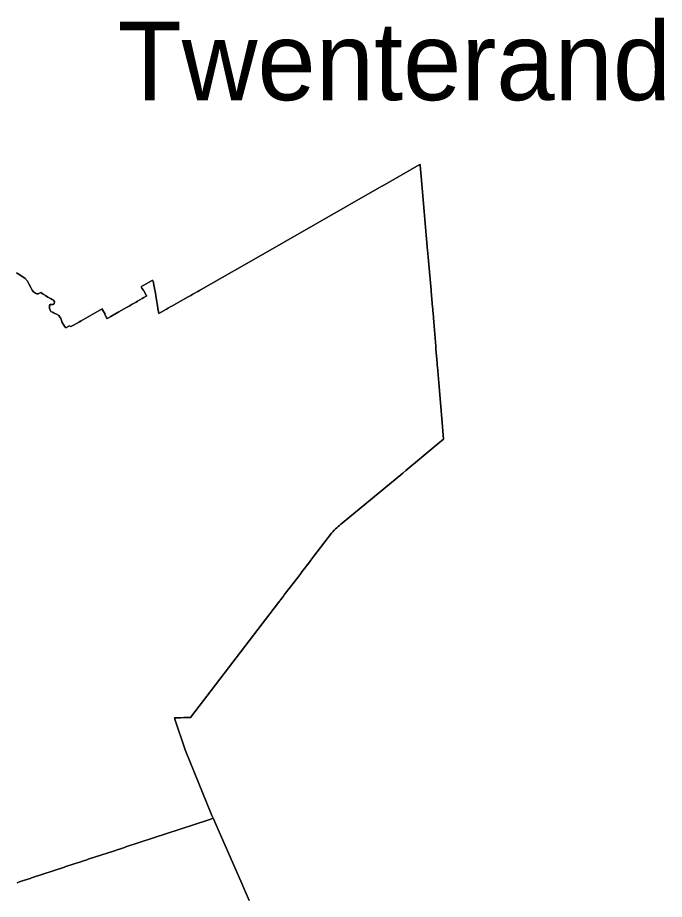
# Model space of a CAD drawing. Extents: x 113371 to 291721, y 393993 to 520143.
# Drawn here: x 234596 to 238723, y 492353 to 497979 of the extents above; entities that cross this region are included whole.
import ezdxf

# ---------------------------------------------------------------- set-up
doc = ezdxf.new("R2010")
doc.units = 0
doc.layers.add('Default', color=7, linetype='Continuous')
doc.layers.add('plaatsnamen', color=7, linetype='Continuous')

msp = doc.modelspace()

# ---------------------------------------------------------------- linework, layer by layer
at = {"layer": 'Default'}
for points in [[(237244.255625, 496130.8725), (237235.055625, 496230.9125), (237234.175625, 496241.0325), (237224.205625, 496356.3625), (237216.105625, 496449.9825), (237213.815625, 496476.4325), (237212.355625, 496493.2425), (237171.465625, 496966.0125), (237165.395625, 497036.2125), (237165.175625, 497038.7025), (237164.825625, 497042.7225), (237164.815625, 497042.7125), (237157.815625, 497038.7225), (236922.145625, 496904.2925), (236921.915625, 496904.1625), (236921.185625, 496903.7425), (236088.645625, 496428.1525), (235856.755625, 496295.9625), (235756.915625, 496238.7625), (235745.675625, 496232.3325), (235745.545625, 496232.2625), (235713.965625, 496214.2225), (235713.875625, 496214.1725), (235700.665625, 496206.6325), (235689.175625, 496200.0425), (235681.025625, 496195.3925), (235580.535625, 496138.0025), (235575.095625, 496135.0625), (235560.105625, 496126.9425), (235557.805625, 496125.6925), (235556.855625, 496125.1825), (235546.935625, 496119.4925), (235497.485625, 496091.0225), (235491.985625, 496124.0025), (235488.835625, 496142.9125), (235487.045625, 496153.7925), (235483.075625, 496177.6425), (235473.675625, 496233.7825)], [(235689.175625, 496200.0425), (235700.665625, 496206.6325), (235713.875625, 496214.1725), (235713.965625, 496214.2225), (235745.545625, 496232.2625), (235745.675625, 496232.3325), (235756.915625, 496238.7625), (235856.755625, 496295.9625), (236088.645625, 496428.1525), (236921.185625, 496903.7425), (236921.915625, 496904.1625), (236922.145625, 496904.2925), (237157.815625, 497038.7225), (237164.815625, 497042.7125), (237164.825625, 497042.7225), (237165.175625, 497038.7025), (237165.395625, 497036.2125), (237171.465625, 496966.0125), (237212.355625, 496493.2425), (237213.815625, 496476.4325), (237216.105625, 496449.9825), (237224.205625, 496356.3625), (237234.175625, 496241.0325), (237235.055625, 496230.9125), (237244.255625, 496130.8725), (237245.225625, 496121.8025), (237246.575625, 496107.4925), (237247.805625, 496093.1525), (237252.315625, 496035.0125), (237264.125625, 495883.0325), (237265.545625, 495864.7025), (237273.005625, 495777.2025), (237274.305625, 495761.9525), (237275.155625, 495751.9325), (237283.985625, 495648.3625), (237303.565625, 495421.8025), (237313.875625, 495289.2825), (237278.365625, 495258.6725)], [(234760.145625, 496215.5825), (234743.595625, 496224.3225), (234727.305625, 496216.8825), (234718.665625, 496216.0025), (234710.255625, 496220.9725), (234697.965625, 496229.0925), (234690.125625, 496240.1525), (234680.615625, 496256.3625), (234668.055625, 496280.8825), (234662.595625, 496293.1425), (234660.665625, 496295.4525), (234644.625625, 496314.5025), (234611.485625, 496338.9725), (234589.775625, 496351.2025)], [(234589.775625, 496351.2025), (234611.485625, 496338.9725), (234644.625625, 496314.5025), (234660.665625, 496295.4525), (234662.595625, 496293.1425), (234668.055625, 496280.8825), (234680.615625, 496256.3625), (234690.125625, 496240.1525), (234697.965625, 496229.0925), (234710.255625, 496220.9725), (234718.665625, 496216.0025), (234727.305625, 496216.8825), (234743.595625, 496224.3225), (234760.145625, 496215.5825), (234774.145625, 496205.4025), (234788.735625, 496194.5425), (234805.665625, 496185.8925), (234816.465625, 496180.4825), (234824.865625, 496175.5425), (234830.675625, 496165.2225), (234830.505625, 496153.2325), (234828.505625, 496150.4825), (234820.925625, 496149.4725), (234815.825625, 496148.4325), (234803.835625, 496148.6125), (234800.555625, 496142.6825), (234799.965625, 496124.0025)], [(235473.675625, 496233.7825), (235472.625625, 496240.0925), (235462.325625, 496297.5025), (235459.205625, 496300.3425), (235458.565625, 496300.9725), (235455.365625, 496301.1925), (235450.325625, 496299.8625), (235430.985625, 496288.6725), (235386.885625, 496263.5925), (235387.845625, 496259.8325), (235390.035625, 496251.2625), (235390.725625, 496251.5825), (235390.965625, 496250.9025), (235398.485625, 496239.0325), (235399.415625, 496239.4725), (235401.455625, 496235.8725), (235417.125625, 496208.2725), (235420.135625, 496203.0825), (235420.115625, 496203.0725), (235401.595625, 496192.4525), (235391.185625, 496186.4825), (235376.135625, 496177.8525), (235361.105625, 496169.2325), (235352.645625, 496164.3825), (235344.185625, 496159.5325), (235327.265625, 496149.8325), (235308.185625, 496138.8925), (235286.515625, 496126.4625), (235243.165625, 496101.6025), (235201.785625, 496077.7225), (235191.425625, 496071.7325), (235172.005625, 496060.5325), (235167.755625, 496058.0725), (235152.055625, 496085.2625), (235154.695625, 496086.7525), (235138.945625, 496115.1925), (235137.385625, 496118.0225), (235136.215625, 496120.1325)], [(235344.185625, 496159.5325), (235352.645625, 496164.3825), (235361.105625, 496169.2325), (235376.135625, 496177.8525), (235391.185625, 496186.4825), (235401.595625, 496192.4525), (235420.115625, 496203.0725), (235420.135625, 496203.0825), (235417.125625, 496208.2725), (235401.455625, 496235.8725), (235399.415625, 496239.4725), (235398.485625, 496239.0325), (235390.965625, 496250.9025), (235390.725625, 496251.5825), (235390.035625, 496251.2625), (235387.845625, 496259.8325), (235386.885625, 496263.5925), (235430.985625, 496288.6725), (235450.325625, 496299.8625), (235455.365625, 496301.1925), (235458.565625, 496300.9725), (235459.205625, 496300.3425), (235462.325625, 496297.5025), (235472.625625, 496240.0925), (235473.675625, 496233.7825), (235483.075625, 496177.6425), (235487.045625, 496153.7925), (235488.835625, 496142.9125), (235491.985625, 496124.0025), (235497.485625, 496091.0225), (235546.935625, 496119.4925), (235556.855625, 496125.1825), (235557.805625, 496125.6925), (235560.105625, 496126.9425), (235575.095625, 496135.0625), (235580.535625, 496138.0025), (235681.025625, 496195.3925), (235689.175625, 496200.0425)], [(235136.215625, 496120.1325), (235121.805625, 496111.9425), (235001.585625, 496043.9425), (234995.055625, 496040.2525), (234993.255625, 496039.2225), (234987.955625, 496036.2125), (234985.335625, 496034.7225), (234941.255625, 496009.6425), (234935.965625, 496006.6325), (234929.235625, 496012.5425), (234929.045625, 496012.7325), (234923.675625, 496009.9925), (234904.735625, 495999.0225), (234899.185625, 496004.0425), (234890.335625, 496016.7225), (234881.715625, 496034.3825), (234873.125625, 496059.4525), (234860.085625, 496077.4825), (234844.575625, 496087.0925), (234829.085625, 496094.0425), (234823.715625, 496096.6425), (234823.465625, 496096.7925), (234808.615625, 496104.5025), (234803.615625, 496111.5225), (234799.965625, 496124.0025), (234800.555625, 496142.6825), (234803.835625, 496148.6125), (234815.825625, 496148.4325), (234820.925625, 496149.4725), (234828.505625, 496150.4825), (234830.505625, 496153.2325), (234830.675625, 496165.2225), (234824.865625, 496175.5425), (234816.465625, 496180.4825), (234805.665625, 496185.8925), (234788.735625, 496194.5425), (234774.145625, 496205.4025), (234760.145625, 496215.5825)], [(234799.965625, 496124.0025), (234803.615625, 496111.5225), (234808.615625, 496104.5025), (234823.465625, 496096.7925), (234823.715625, 496096.6425), (234829.085625, 496094.0425), (234844.575625, 496087.0925), (234860.085625, 496077.4825), (234873.125625, 496059.4525), (234881.715625, 496034.3825), (234890.335625, 496016.7225), (234899.185625, 496004.0425), (234904.735625, 495999.0225), (234923.675625, 496009.9925), (234929.045625, 496012.7325), (234929.235625, 496012.5425), (234935.965625, 496006.6325), (234941.255625, 496009.6425), (234985.335625, 496034.7225), (234987.955625, 496036.2125), (234993.255625, 496039.2225), (234995.055625, 496040.2525), (235001.585625, 496043.9425), (235121.805625, 496111.9425), (235136.215625, 496120.1325), (235137.385625, 496118.0225), (235138.945625, 496115.1925), (235154.695625, 496086.7525), (235152.055625, 496085.2625), (235167.755625, 496058.0725), (235172.005625, 496060.5325), (235191.425625, 496071.7325), (235201.785625, 496077.7225), (235243.165625, 496101.6025), (235286.515625, 496126.4625), (235308.185625, 496138.8925), (235327.265625, 496149.8325), (235344.185625, 496159.5325)], [(236403.685625, 494433.4425), (236410.915625, 494442.8825), (236435.505625, 494474.9725), (236442.535625, 494483.8225), (236446.595625, 494488.7725), (236447.385625, 494489.8625), (236468.125625, 494518.1525), (236465.945625, 494513.7925), (236468.155625, 494516.6825), (236487.265625, 494542.3325), (236598.675625, 494689.3125), (236607.025625, 494699.2925), (236615.315625, 494707.9625), (236624.385625, 494716.9425), (236632.595625, 494724.3225), (236641.755625, 494732.1225), (236650.825625, 494739.3525), (236659.775625, 494746.7525), (236667.355625, 494752.9225), (236861.005625, 494913.9225), (237053.415625, 495073.5225), (237072.595625, 495089.7925), (237161.565625, 495162.5325), (237175.705625, 495174.1725), (237278.365625, 495258.6725), (237313.875625, 495289.2825), (237303.565625, 495421.8025), (237283.985625, 495648.3625), (237275.155625, 495751.9325), (237274.305625, 495761.9525), (237273.005625, 495777.2025), (237265.545625, 495864.7025), (237264.125625, 495883.0325), (237252.315625, 496035.0125), (237247.805625, 496093.1525), (237246.575625, 496107.4925), (237245.225625, 496121.8025), (237244.255625, 496130.8725)], [(237278.365625, 495258.6725), (237175.705625, 495174.1725), (237161.565625, 495162.5325), (237072.595625, 495089.7925), (237053.415625, 495073.5225), (236861.005625, 494913.9225), (236667.355625, 494752.9225), (236659.775625, 494746.7525), (236650.825625, 494739.3525), (236641.755625, 494732.1225), (236632.595625, 494724.3225), (236624.385625, 494716.9425), (236615.315625, 494707.9625), (236607.025625, 494699.2925), (236598.675625, 494689.3125), (236487.265625, 494542.3325), (236468.155625, 494516.6825), (236465.945625, 494513.7925), (236468.125625, 494518.1525), (236447.385625, 494489.8625), (236446.595625, 494488.7725), (236442.535625, 494483.8225), (236435.505625, 494474.9725), (236410.915625, 494442.8825), (236403.685625, 494433.4425), (236383.405625, 494406.9225), (236298.085625, 494295.3425), (236291.895625, 494287.2525), (236285.935625, 494279.4925), (236274.085625, 494264.0425), (236271.865625, 494261.1925), (236269.705625, 494258.4125), (236261.685625, 494247.9025), (235698.535625, 493513.9225), (235659.075625, 493513.0325), (235656.135625, 493512.9725), (235634.795625, 493512.6225), (235633.985625, 493512.6125)], [(234917.605625, 492566.4025), (234938.025625, 492573.1025), (234964.185625, 492581.6925), (234993.695625, 492591.3725), (234999.475625, 492593.2725), (235009.705625, 492596.6225), (235037.895625, 492605.8825), (235047.195625, 492608.9325), (235214.085625, 492663.7225), (235238.345625, 492671.6825), (235240.325625, 492672.3325), (235278.395625, 492684.8225), (235287.465625, 492687.8025), (235809.845625, 492859.2725), (235816.175625, 492861.3625), (235833.145625, 492866.9325), (235844.055625, 492870.5025), (235835.805625, 492889.2925), (235666.335625, 493306.3625), (235599.715625, 493502.8925), (235596.585625, 493512.0725), (235600.805625, 493512.0625), (235617.145625, 493512.3325), (235626.085625, 493512.4825), (235633.985625, 493512.6125), (235634.795625, 493512.6225), (235656.135625, 493512.9725), (235659.075625, 493513.0325), (235698.535625, 493513.9225), (236261.685625, 494247.9025), (236269.705625, 494258.4125), (236271.865625, 494261.1925), (236274.085625, 494264.0425), (236285.935625, 494279.4925), (236291.895625, 494287.2525), (236298.085625, 494295.3425), (236383.405625, 494406.9225), (236403.685625, 494433.4425)], [(235633.985625, 493512.6125), (235626.085625, 493512.4825), (235617.145625, 493512.3325), (235600.805625, 493512.0625), (235596.585625, 493512.0725), (235599.715625, 493502.8925), (235666.335625, 493306.3625), (235835.805625, 492889.2925), (235844.055625, 492870.5025), (236020.275625, 492468.7525), (236074.375625, 492345.4125)], [(236074.375625, 492345.4125), (236020.275625, 492468.7525), (235844.055625, 492870.5025), (235833.145625, 492866.9325), (235816.175625, 492861.3625), (235809.845625, 492859.2725), (235287.465625, 492687.8025), (235278.395625, 492684.8225), (235240.325625, 492672.3325), (235238.345625, 492671.6825), (235214.085625, 492663.7225), (235047.195625, 492608.9325), (235037.895625, 492605.8825), (235009.705625, 492596.6225), (234999.475625, 492593.2725), (234993.695625, 492591.3725), (234964.185625, 492581.6925), (234938.025625, 492573.1025), (234917.605625, 492566.4025), (234898.315625, 492560.0725), (234895.625625, 492559.1925), (234685.195625, 492490.1425), (234676.265625, 492487.2125), (234634.805625, 492473.6125), (234621.025625, 492469.0925), (234614.125625, 492466.8225), (234611.735625, 492466.8125), (234594.195625, 492459.8025)], [(234594.195625, 492459.8025), (234611.735625, 492466.8125), (234614.125625, 492466.8225), (234621.025625, 492469.0925), (234634.805625, 492473.6125), (234676.265625, 492487.2125), (234685.195625, 492490.1425), (234895.625625, 492559.1925), (234898.315625, 492560.0725), (234917.605625, 492566.4025)]]:
    msp.add_lwpolyline(points, dxfattribs=at)

# ---------------------------------------------------------------- texts
at = {"layer": 'plaatsnamen'}
msp.add_text('Twenterand', height=500, dxfattribs=at).set_placement((235235.454379, 497452.24857))

doc.saveas('drawing.dxf')
